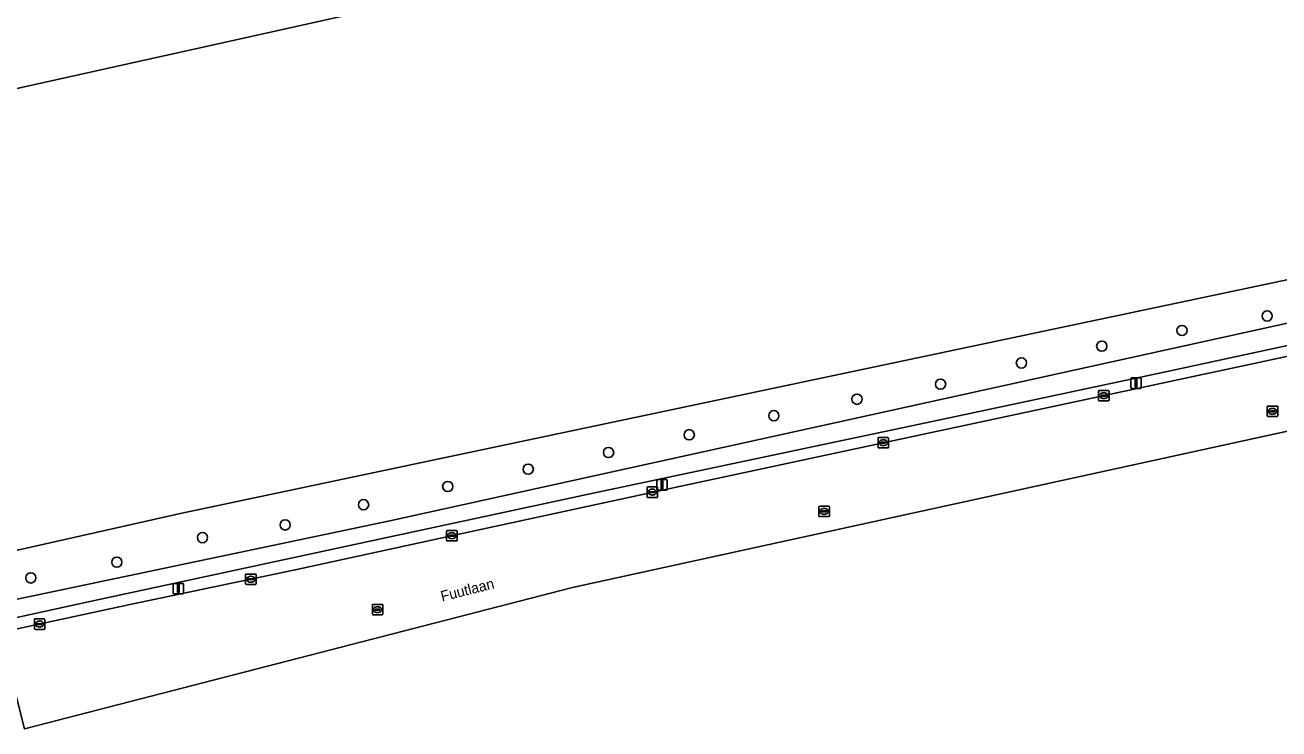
# Model space of a CAD drawing. Extents: x 161477 to 163040, y 383680 to 384871.
# Drawn here: x 161899 to 162018.6, y 383706.6 to 383773.8 of the extents above; entities that cross this region are included whole.
import ezdxf

# ---------------------------------------------------------------- set-up
doc = ezdxf.new("R2010")
doc.units = 0
for name, color, linetype in [('IMGEO_Boom', 7, 'Continuous'), ('IMGEO_Erf', 7, 'Continuous'), ('IMGEO_Groenvoorziening', 7, 'Continuous'), ('IMGEO_Hek', 7, 'Continuous'), ('IMGEO_Kolk', 7, 'Continuous'), ('IMGEO_Lichtmast', 7, 'Continuous'), ('IMGEO_Openbare_ruimte_label', 7, 'Continuous'), ('IMGEO_Pand', 7, 'Continuous'), ('IMGEO_Rijbaan_lokaal_open', 7, 'Continuous'), ('IMGEO_Rioolput', 7, 'Continuous'), ('IMGEO_Voetpad_open', 7, 'Continuous')]:
    doc.layers.add(name, color=color, linetype=linetype)

msp = doc.modelspace()

# ---------------------------------------------------------------- linework, layer by layer
at = {"layer": 'IMGEO_Boom'}
for centre in [(162017.44, 383746.01), (162009.32, 383744.63), (162001.67, 383743.13), (161994.01, 383741.53), (161986.3, 383739.51), (161978.33, 383738.07), (161970.4, 383736.5), (161962.33, 383734.68), (161954.64, 383732.99), (161946.98, 383731.4), (161939.31, 383729.75), (161931.28, 383728.01), (161923.8, 383726.08), (161915.92, 383724.87), (161907.75, 383722.53), (161899.55, 383721.03)]:
    msp.add_circle(centre, 0.489, dxfattribs=at)
at = {"layer": 'IMGEO_Erf'}
for points in [[(162126.91, 383818.18), (162000, 383790.34), (161890.45, 383765.98)], [(161882.57, 383720.16), (161913.96, 383727.2), (162034.23, 383752.62)]]:
    msp.add_lwpolyline(points, dxfattribs=at)
at = {"layer": 'IMGEO_Groenvoorziening'}
for points in [[(162034.23, 383752.62), (161913.96, 383727.2), (161882.57, 383720.16), (161862.58, 383715.7), (161851.78, 383713.8), (161847.77, 383713.09), (161846.44, 383712.85), (161845.48, 383712.89), (161845.45, 383711.91), (161851.16, 383711.93), (161854.98, 383712.1), (161860.05, 383712.34), (161872.38, 383713.55), (161933.79, 383726.48), (162037.84, 383749.41)], [(162037.84, 383749.41), (161933.79, 383726.48), (161872.38, 383713.55), (161876.5, 383713.96), (161886.43, 383715.07), (161895.43, 383716.66), (161904.89, 383718.7), (161934.1, 383725.01), (161953.18, 383729.12), (161987.59, 383736.39), (162007.91, 383740.73), (162033.22, 383746.19)]]:
    msp.add_lwpolyline(points, dxfattribs=at)
at = {"layer": 'IMGEO_Hek'}
msp.add_lwpolyline([(161846.44, 383712.85), (161847.77, 383713.09), (161851.78, 383713.8), (161862.58, 383715.7), (161882.57, 383720.16), (161913.96, 383727.2), (162034.23, 383752.62), (162061.02, 383757.62)], dxfattribs=at)
at = {"layer": 'IMGEO_Kolk'}
for p, q in [((162001.43, 383738.91), (162002.28, 383738.91)), ((162001.35, 383737.98), (162001.35, 383738.83)), ((162002.28, 383737.91), (162001.43, 383737.91)), ((162001.61, 383738.4), (162001.61, 383738.41)), ((162002.05, 383738.36), (162001.65, 383738.36)), ((162001.66, 383738.45), (162002.05, 383738.45)), ((162001.84, 383738.69), (162001.87, 383738.69)), ((162001.86, 383738.13), (162001.84, 383738.13)), ((162002.1, 383738.41), (162002.1, 383738.4)), ((162002.36, 383738.83), (162002.36, 383737.98)), ((161980.34, 383733.5), (161980.34, 383734.36)), ((161980.41, 383734.43), (161981.27, 383734.43)), ((161980.83, 383734.21), (161980.85, 383734.21)), ((161981.34, 383734.36), (161981.34, 383733.5)), ((161981.27, 383733.43), (161980.41, 383733.43)), ((161980.6, 383733.92), (161980.6, 383733.94)), ((161980.64, 383733.97), (161981.04, 383733.97)), ((161981.03, 383733.89), (161980.64, 383733.89)), ((161980.85, 383733.65), (161980.82, 383733.65)), ((161981.08, 383733.94), (161981.08, 383733.92)), ((161958.31, 383728.78), (161958.31, 383729.63)), ((161958.39, 383729.71), (161959.24, 383729.71)), ((161958.8, 383729.49), (161958.83, 383729.49)), ((161959.31, 383729.63), (161959.31, 383728.78)), ((161959.24, 383728.71), (161958.39, 383728.71)), ((161958.57, 383729.2), (161958.57, 383729.21)), ((161958.61, 383729.25), (161959.01, 383729.25)), ((161959.01, 383729.16), (161958.61, 383729.16)), ((161958.82, 383728.93), (161958.8, 383728.93)), ((161959.06, 383729.21), (161959.06, 383729.2)), ((161939.2, 383724.62), (161939.2, 383725.48)), ((161939.27, 383725.55), (161940.12, 383725.55)), ((161939.46, 383725.04), (161939.46, 383725.06)), ((161939.5, 383725.09), (161939.9, 383725.09)), ((161939.89, 383725.01), (161939.5, 383725.01)), ((161939.71, 383724.77), (161939.68, 383724.77)), ((161939.69, 383725.33), (161939.71, 383725.33)), ((161939.94, 383725.06), (161939.94, 383725.04)), ((161940.2, 383725.48), (161940.2, 383724.62)), ((161940.12, 383724.55), (161939.27, 383724.55)), ((161920.03, 383720.47), (161920.03, 383721.33)), ((161920.1, 383721.4), (161920.95, 383721.4)), ((161920.51, 383721.18), (161920.54, 383721.18)), ((161921.03, 383721.33), (161921.03, 383720.47)), ((161920.95, 383720.4), (161920.1, 383720.4)), ((161920.28, 383720.89), (161920.28, 383720.91)), ((161920.72, 383720.86), (161920.32, 383720.86)), ((161920.33, 383720.94), (161920.73, 383720.94)), ((161920.54, 383720.62), (161920.51, 383720.62)), ((161920.77, 383720.91), (161920.77, 383720.89)), ((161899.89, 383716.19), (161899.89, 383717.05)), ((161899.96, 383717.12), (161900.82, 383717.12)), ((161900.15, 383716.61), (161900.15, 383716.63)), ((161900.19, 383716.66), (161900.59, 383716.66)), ((161900.59, 383716.58), (161900.19, 383716.58)), ((161900.38, 383716.9), (161900.4, 383716.9)), ((161900.4, 383716.34), (161900.38, 383716.34)), ((161900.63, 383716.63), (161900.63, 383716.61)), ((161900.89, 383717.05), (161900.89, 383716.19)), ((161900.82, 383716.12), (161899.96, 383716.12))]:
    msp.add_line(p, q, dxfattribs=at)
for points in [[(162001.43, 383738.91), (162002.28, 383738.91)], [(162001.35, 383737.98), (162001.35, 383738.83)], [(162002.28, 383737.91), (162001.43, 383737.91)], [(162002.36, 383738.83), (162002.36, 383737.98)], [(161980.34, 383733.5), (161980.34, 383734.36)], [(161980.41, 383734.43), (161981.27, 383734.43)], [(161981.34, 383734.36), (161981.34, 383733.5)], [(161981.27, 383733.43), (161980.41, 383733.43)], [(161958.31, 383728.78), (161958.31, 383729.63)], [(161958.39, 383729.71), (161959.24, 383729.71)], [(161959.31, 383729.63), (161959.31, 383728.78)], [(161959.24, 383728.71), (161958.39, 383728.71)], [(161939.2, 383724.62), (161939.2, 383725.48)], [(161939.27, 383725.55), (161940.12, 383725.55)], [(161940.2, 383725.48), (161940.2, 383724.62)], [(161940.12, 383724.55), (161939.27, 383724.55)], [(161920.03, 383720.47), (161920.03, 383721.33)], [(161920.1, 383721.4), (161920.95, 383721.4)], [(161921.03, 383721.33), (161921.03, 383720.47)], [(161920.95, 383720.4), (161920.1, 383720.4)], [(161899.89, 383716.19), (161899.89, 383717.05)], [(161899.96, 383717.12), (161900.82, 383717.12)], [(161900.89, 383717.05), (161900.89, 383716.19)], [(161900.82, 383716.12), (161899.96, 383716.12)]]:
    msp.add_lwpolyline(points, dxfattribs=at)
for centre, radius, start, end in [((162001.43, 383738.83), 0.0765, 91.552, 178.448), ((162001.43, 383738.83), 0.0765, 91.552, 178.448), ((162002.28, 383738.83), 0.0765, 1.552, 88.448), ((162002.28, 383738.83), 0.0765, 1.552, 88.448), ((162001.43, 383737.98), 0.0765, 181.552, 268.448), ((162001.43, 383737.98), 0.0765, 181.552, 268.448), ((162001.65, 383738.41), 0.0403, 85.8775, 175.7526), ((162001.65, 383738.4), 0.0366, 178.938, 274.7102), ((162002.06, 383738.41), 0.0386, 1.7309, 96.639), ((162002.05, 383738.41), 0.043, 264.8664, 352.4533), ((162002.28, 383737.98), 0.0765, 271.552, 358.448), ((162002.28, 383737.98), 0.0765, 271.552, 358.448), ((161980.41, 383734.35), 0.0765, 91.552, 178.448), ((161980.41, 383734.35), 0.0765, 91.552, 178.448), ((161981.26, 383734.35), 0.0765, 1.552, 88.448), ((161981.26, 383734.35), 0.0765, 1.552, 88.448), ((161980.41, 383733.5), 0.0765, 181.552, 268.448), ((161980.41, 383733.5), 0.0765, 181.552, 268.448), ((161980.64, 383733.93), 0.0403, 85.8775, 175.7526), ((161980.63, 383733.92), 0.0366, 178.938, 274.7102), ((161981.04, 383733.93), 0.043, 264.8664, 352.4533), ((161981.04, 383733.93), 0.0386, 1.7309, 96.639), ((161981.26, 383733.5), 0.0765, 271.552, 358.448), ((161981.26, 383733.5), 0.0765, 271.552, 358.448), ((161958.39, 383729.63), 0.0765, 91.552, 178.448), ((161958.39, 383729.63), 0.0765, 91.552, 178.448), ((161959.24, 383729.63), 0.0765, 1.552, 88.448), ((161959.24, 383729.63), 0.0765, 1.552, 88.448), ((161958.39, 383728.78), 0.0765, 181.552, 268.448), ((161958.39, 383728.78), 0.0765, 181.552, 268.448), ((161958.61, 383729.21), 0.0403, 85.8775, 175.7526), ((161958.61, 383729.2), 0.0366, 178.938, 274.7102), ((161959.02, 383729.21), 0.0386, 1.7309, 96.639), ((161959.01, 383729.21), 0.043, 264.8664, 352.4533), ((161959.24, 383728.78), 0.0765, 271.552, 358.448), ((161959.24, 383728.78), 0.0765, 271.552, 358.448), ((161939.27, 383725.47), 0.0765, 91.552, 178.448), ((161939.27, 383725.47), 0.0765, 91.552, 178.448), ((161939.27, 383724.63), 0.0765, 181.552, 268.448), ((161939.27, 383724.63), 0.0765, 181.552, 268.448), ((161939.5, 383725.05), 0.0403, 85.8775, 175.7526), ((161939.49, 383725.04), 0.0366, 178.938, 274.7102), ((161939.9, 383725.05), 0.043, 264.8664, 352.4533), ((161939.9, 383725.05), 0.0386, 1.7309, 96.639), ((161940.12, 383725.47), 0.0765, 1.552, 88.448), ((161940.12, 383725.47), 0.0765, 1.552, 88.448), ((161940.12, 383724.63), 0.0765, 271.552, 358.448), ((161940.12, 383724.63), 0.0765, 271.552, 358.448), ((161920.1, 383721.32), 0.0765, 91.552, 178.448), ((161920.1, 383721.32), 0.0765, 91.552, 178.448), ((161920.95, 383721.32), 0.0765, 1.552, 88.448), ((161920.95, 383721.32), 0.0765, 1.552, 88.448), ((161920.1, 383720.48), 0.0765, 181.552, 268.448), ((161920.1, 383720.48), 0.0765, 181.552, 268.448), ((161920.33, 383720.9), 0.0403, 85.8775, 175.7526), ((161920.32, 383720.89), 0.0366, 178.938, 274.7102), ((161920.73, 383720.9), 0.043, 264.8664, 352.4533), ((161920.73, 383720.9), 0.0386, 1.7309, 96.639), ((161920.95, 383720.48), 0.0765, 271.552, 358.448), ((161920.95, 383720.48), 0.0765, 271.552, 358.448), ((161899.97, 383717.05), 0.0765, 91.552, 178.448), ((161899.97, 383717.05), 0.0765, 91.552, 178.448), ((161899.97, 383716.2), 0.0765, 181.552, 268.448), ((161899.97, 383716.2), 0.0765, 181.552, 268.448), ((161900.19, 383716.62), 0.0403, 85.8775, 175.7526), ((161900.19, 383716.61), 0.0366, 178.938, 274.7102), ((161900.59, 383716.63), 0.0386, 1.7309, 96.639), ((161900.59, 383716.62), 0.043, 264.8664, 352.4533), ((161900.81, 383717.05), 0.0765, 1.552, 88.448), ((161900.81, 383717.05), 0.0765, 1.552, 88.448), ((161900.81, 383716.2), 0.0765, 271.552, 358.448), ((161900.81, 383716.2), 0.0765, 271.552, 358.448)]:
    msp.add_arc(centre, radius, start, end, dxfattribs=at)
for centre, major_axis, ratio, start_param, end_param in [((162001.84, 383738.41), (-0.387, 0.002), 0.722429, 4.712389, 7.853982), ((162001.87, 383738.41), (-0.39, 0.002), 0.717154, 1.570796, 4.712389), ((161980.83, 383733.93), (-0.387, 0.002), 0.722429, 4.712389, 7.853982), ((161980.85, 383733.93), (-0.39, 0.002), 0.717154, 1.570796, 4.712389), ((161958.8, 383729.21), (-0.387, 0.002), 0.722429, 4.712389, 7.853982), ((161958.82, 383729.21), (-0.39, 0.002), 0.717154, 1.570796, 4.712389), ((161939.68, 383725.05), (-0.387, 0.002), 0.722429, 4.712389, 7.853982), ((161939.71, 383725.05), (-0.39, 0.002), 0.717154, 1.570796, 4.712389), ((161920.51, 383720.9), (-0.387, 0.002), 0.722429, 4.712389, 7.853982), ((161920.54, 383720.9), (-0.39, 0.002), 0.717154, 1.570796, 4.712389), ((161900.38, 383716.62), (-0.387, 0.002), 0.722429, 4.712389, 7.853982), ((161900.4, 383716.62), (-0.39, 0.002), 0.717154, 1.570796, 4.712389)]:
    msp.add_ellipse(centre, major_axis=major_axis, ratio=ratio, start_param=start_param, end_param=end_param, dxfattribs=at)
at = {"layer": 'IMGEO_Lichtmast'}
for p, q in [((162004.55, 383740.11), (162005.34, 383740.11)), ((162005.34, 383740.11), (162004.55, 383740.11)), ((162004.45, 383739.21), (162004.45, 383740.01)), ((162004.45, 383740.01), (162004.45, 383739.21)), ((162005.34, 383739.11), (162004.55, 383739.11)), ((162004.55, 383739.11), (162005.34, 383739.11)), ((162005.44, 383740.01), (162005.44, 383739.21)), ((162005.44, 383739.21), (162005.44, 383740.01)), ((161959.25, 383729.5), (161959.25, 383730.3)), ((161959.25, 383730.3), (161959.25, 383729.5)), ((161959.35, 383730.4), (161960.14, 383730.4)), ((161960.14, 383730.4), (161959.35, 383730.4)), ((161960.14, 383729.4), (161959.35, 383729.4)), ((161959.35, 383729.4), (161960.14, 383729.4)), ((161960.24, 383730.3), (161960.24, 383729.5)), ((161960.24, 383729.5), (161960.24, 383730.3)), ((161913.11, 383719.61), (161913.11, 383720.41)), ((161913.11, 383720.41), (161913.11, 383719.61)), ((161913.21, 383720.51), (161914, 383720.51)), ((161914, 383720.51), (161913.21, 383720.51)), ((161914.1, 383720.41), (161914.1, 383719.61)), ((161914.1, 383719.61), (161914.1, 383720.41)), ((161914, 383719.51), (161913.21, 383719.51)), ((161913.21, 383719.51), (161914, 383719.51))]:
    msp.add_line(p, q, dxfattribs=at)
for points in [[(162004.87, 383739.99), (162005.02, 383739.99), (162005.02, 383739.24), (162004.87, 383739.24), (162004.87, 383739.99)], [(161959.67, 383730.28), (161959.82, 383730.28), (161959.82, 383729.53), (161959.67, 383729.53), (161959.67, 383730.28)], [(161913.53, 383720.39), (161913.68, 383720.39), (161913.68, 383719.64), (161913.53, 383719.64), (161913.53, 383720.39)]]:
    msp.add_lwpolyline(points, dxfattribs=at)
for centre, start, end in [((162004.55, 383740.01), 90, 180), ((162004.55, 383740.01), 90, 180), ((162005.34, 383740.01), 0, 90), ((162005.34, 383740.01), 360, 90), ((162004.55, 383739.21), 180, 270), ((162004.55, 383739.21), 180, 270), ((162005.34, 383739.21), 270, 0), ((162005.34, 383739.21), 270, 0), ((161959.35, 383730.3), 90, 180), ((161959.35, 383730.3), 90, 180), ((161959.35, 383729.5), 180, 270), ((161959.35, 383729.5), 180, 270), ((161960.14, 383730.3), 0, 90), ((161960.14, 383730.3), 360, 90), ((161960.14, 383729.5), 270, 0), ((161960.14, 383729.5), 270, 0), ((161913.21, 383720.41), 90, 180), ((161913.21, 383720.41), 90, 180), ((161914, 383720.41), 0, 90), ((161914, 383720.41), 360, 90), ((161913.21, 383719.61), 180, 270), ((161913.21, 383719.61), 180, 270), ((161914, 383719.61), 270, 0), ((161914, 383719.61), 270, 0)]:
    msp.add_arc(centre, 0.1, start, end, dxfattribs=at)
at = {"layer": 'IMGEO_Pand'}
msp.add_lwpolyline([(162088.04, 383839.79), (162000, 383820.13), (161884.78, 383794.45), (161884.66, 383795.01), (161884.29, 383794.93), (161884.34, 383794.72), (161884.38, 383794.54), (161884.16, 383794.49), (161884.31, 383793.82), (161888.73, 383773.98), (161886.05, 383773.38), (161886.3, 383772.28), (161885.88, 383772.17), (161885.51, 383773.82), (161859.41, 383768), (161862.46, 383754.35), (161888.64, 383760.19), (161888.12, 383762.5), (161887.37, 383765.86), (161890.33, 383766.52), (161890.45, 383765.98), (162000, 383790.34), (162126.91, 383818.18)], dxfattribs=at)
at = {"layer": 'IMGEO_Rijbaan_lokaal_open'}
msp.add_lwpolyline([(162038.61, 383746.29), (162000, 383738.01), (161982.31, 383734.24), (161961.39, 383729.76), (161941.41, 383725.42), (161924.76, 383721.79), (161909.3, 383718.55), (161896.63, 383715.81), (161898.95, 383706.62), (161898.95, 383706.62), (161951.21, 383720.12), (162050.78, 383741.89)], dxfattribs=at)
at = {"layer": 'IMGEO_Rioolput'}
for p, q in [((162017.45, 383736.49), (162017.45, 383737.35)), ((162017.52, 383737.42), (162018.37, 383737.42)), ((162017.7, 383736.91), (162017.7, 383736.93)), ((162018.14, 383736.88), (162017.74, 383736.88)), ((162017.75, 383736.96), (162018.14, 383736.96)), ((162017.93, 383737.2), (162017.96, 383737.2)), ((162017.96, 383736.64), (162017.93, 383736.64)), ((162018.19, 383736.93), (162018.19, 383736.91)), ((162018.45, 383737.35), (162018.45, 383736.49)), ((162018.37, 383736.42), (162017.52, 383736.42)), ((161974.7, 383726.95), (161974.7, 383727.8)), ((161974.77, 383727.88), (161975.62, 383727.88)), ((161974.95, 383727.37), (161974.95, 383727.38)), ((161975.39, 383727.33), (161974.99, 383727.33)), ((161975, 383727.42), (161975.4, 383727.42)), ((161975.18, 383727.65), (161975.21, 383727.65)), ((161975.21, 383727.1), (161975.18, 383727.1)), ((161975.44, 383727.38), (161975.44, 383727.37)), ((161975.7, 383727.8), (161975.7, 383726.95)), ((161975.62, 383726.87), (161974.77, 383726.87)), ((161932.12, 383717.58), (161932.12, 383718.43)), ((161932.19, 383718.5), (161933.04, 383718.5)), ((161933.04, 383717.5), (161932.19, 383717.5)), ((161932.37, 383718), (161932.37, 383718.01)), ((161932.81, 383717.96), (161932.41, 383717.96)), ((161932.42, 383718.05), (161932.82, 383718.05)), ((161932.6, 383718.28), (161932.63, 383718.28)), ((161932.63, 383717.72), (161932.6, 383717.72)), ((161932.86, 383718.01), (161932.86, 383718)), ((161933.12, 383718.43), (161933.12, 383717.58))]:
    msp.add_line(p, q, dxfattribs=at)
for points in [[(162017.45, 383736.49), (162017.45, 383737.35)], [(162017.52, 383737.42), (162018.37, 383737.42)], [(162018.45, 383737.35), (162018.45, 383736.49)], [(162018.37, 383736.42), (162017.52, 383736.42)], [(161974.7, 383726.95), (161974.7, 383727.8)], [(161974.77, 383727.88), (161975.62, 383727.88)], [(161975.7, 383727.8), (161975.7, 383726.95)], [(161975.62, 383726.87), (161974.77, 383726.87)], [(161932.12, 383717.58), (161932.12, 383718.43)], [(161932.19, 383718.5), (161933.04, 383718.5)], [(161933.04, 383717.5), (161932.19, 383717.5)], [(161933.12, 383718.43), (161933.12, 383717.58)]]:
    msp.add_lwpolyline(points, dxfattribs=at)
for centre, radius, start, end in [((162017.52, 383737.35), 0.0765, 91.552, 178.448), ((162017.52, 383737.35), 0.0765, 91.552, 178.448), ((162017.74, 383736.92), 0.0403, 85.8775, 175.7526), ((162017.74, 383736.91), 0.0366, 178.938, 274.7102), ((162018.15, 383736.93), 0.0386, 1.7309, 96.639), ((162018.15, 383736.92), 0.043, 264.8664, 352.4533), ((162018.37, 383737.35), 0.0765, 1.552, 88.448), ((162018.37, 383737.35), 0.0765, 1.552, 88.448), ((162017.52, 383736.5), 0.0765, 181.552, 268.448), ((162017.52, 383736.5), 0.0765, 181.552, 268.448), ((162018.37, 383736.5), 0.0765, 271.552, 358.448), ((162018.37, 383736.5), 0.0765, 271.552, 358.448), ((161974.77, 383727.8), 0.0765, 91.552, 178.448), ((161974.77, 383727.8), 0.0765, 91.552, 178.448), ((161974.77, 383726.95), 0.0765, 181.552, 268.448), ((161974.77, 383726.95), 0.0765, 181.552, 268.448), ((161975, 383727.38), 0.0403, 85.8775, 175.7526), ((161974.99, 383727.37), 0.0366, 178.938, 274.7102), ((161975.4, 383727.37), 0.043, 264.8664, 352.4533), ((161975.4, 383727.38), 0.0386, 1.7309, 96.639), ((161975.62, 383727.8), 0.0765, 1.552, 88.448), ((161975.62, 383727.8), 0.0765, 1.552, 88.448), ((161975.62, 383726.95), 0.0765, 271.552, 358.448), ((161975.62, 383726.95), 0.0765, 271.552, 358.448), ((161932.19, 383718.43), 0.0765, 91.552, 178.448), ((161932.19, 383718.43), 0.0765, 91.552, 178.448), ((161932.19, 383717.58), 0.0765, 181.552, 268.448), ((161932.19, 383717.58), 0.0765, 181.552, 268.448), ((161932.42, 383718.01), 0.0403, 85.8775, 175.7526), ((161932.41, 383718), 0.0366, 178.938, 274.7102), ((161932.82, 383718), 0.043, 264.8664, 352.4533), ((161932.82, 383718.01), 0.0386, 1.7309, 96.639), ((161933.04, 383718.43), 0.0765, 1.552, 88.448), ((161933.04, 383718.43), 0.0765, 1.552, 88.448), ((161933.04, 383717.58), 0.0765, 271.552, 358.448), ((161933.04, 383717.58), 0.0765, 271.552, 358.448)]:
    msp.add_arc(centre, radius, start, end, dxfattribs=at)
for centre, major_axis, ratio, start_param, end_param in [((162017.93, 383736.92), (-0.387, 0.002), 0.722429, 4.712389, 7.853982), ((162017.96, 383736.92), (-0.39, 0.002), 0.717154, 1.570796, 4.712389), ((161975.18, 383727.37), (-0.387, 0.002), 0.722429, 4.712389, 7.853982), ((161975.21, 383727.37), (-0.39, 0.002), 0.717154, 1.570796, 4.712389), ((161932.6, 383718), (-0.387, 0.002), 0.722429, 4.712389, 7.853982), ((161932.63, 383718), (-0.39, 0.002), 0.717154, 1.570796, 4.712389)]:
    msp.add_ellipse(centre, major_axis=major_axis, ratio=ratio, start_param=start_param, end_param=end_param, dxfattribs=at)
at = {"layer": 'IMGEO_Voetpad_open'}
for points in [[(162033.22, 383746.19), (162007.91, 383740.73), (161987.59, 383736.39), (161953.18, 383729.12), (161934.1, 383725.01), (161904.89, 383718.7), (161895.43, 383716.66), (161886.43, 383715.07), (161876.5, 383713.96), (161872.38, 383713.55), (161860.05, 383712.34), (161854.98, 383712.1), (161851.16, 383711.93), (161845.45, 383711.91), (161845.73, 383710.88), (161845.75, 383710.87), (161845.78, 383710.87), (161845.8, 383710.86), (161845.82, 383710.86), (161846.35, 383710.85)], [(161881.01, 383713.35), (161883.06, 383713.65), (161885.42, 383713.97), (161888.36, 383714.41), (161892.08, 383715.1), (161894.39, 383715.56), (161896.6, 383715.92), (161896.63, 383715.81), (161909.3, 383718.55), (161924.76, 383721.79), (161941.41, 383725.42), (161961.39, 383729.76), (161982.31, 383734.24), (162000, 383738.01), (162038.61, 383746.29)]]:
    msp.add_lwpolyline(points, dxfattribs=at)

# ---------------------------------------------------------------- texts
at = {"layer": 'IMGEO_Openbare_ruimte_label'}
msp.add_text('Fuutlaan', height=1, rotation=14.1751, dxfattribs=at).set_placement((161938.77, 383718.77))

doc.saveas('drawing.dxf')
